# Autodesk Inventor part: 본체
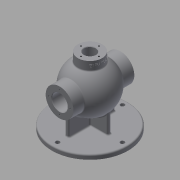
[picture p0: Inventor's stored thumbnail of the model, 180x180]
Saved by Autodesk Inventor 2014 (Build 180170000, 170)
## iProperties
Created: 2020-08
Part Number: 본체
Material: Generic
Document SubType Name: Modeling
Designer: kh
Density: 1 g/cm^3
Appearance: Default
Mass: 648.932 g
Surface Area: 1343.83 cm^2
Volume: 648.932 cm^3
Author: kh
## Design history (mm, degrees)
sketch "Sketch1"
  geometry: C1 r 85 at (0, 0); 1 further point
  constraints: 1 centre point, 1 coincident
  dimensions: "d0" = 170 diameter of C1
extrude "Extrusion1" new body sketch "Sketch1" distance "d1" = 10; taper "d2" = 0 deg
sketch "Sketch3"
  geometry: L1 (-53, 85)-(53, 85); L2 (-53, 85)-(-43, 85); L3 (43, 85)-(53, 85); A1 r 53 centre (0, 85) between (-53, 85) and (53, 85); A2 r 43 centre (0, 85) between (-43, 85) and (43, 85); 1 further point
  constraints: 6 end point, 4 point on circle, 2 centre point, 2 midpoint, 2 point on line, 1 collinear, 1 horizontal, 1 vertical alignment
  dimensions: "d22" = 106 diameter of A1; "d23" = 85 distance of point (0, 0) A1.centre; "d38" = 86 diameter of A2
revolve "Revolution4" sketch "Sketch3" stored, may be unused: angle "d39" = 90 deg
sketch "Sketch4"
  geometry: L1 (-85.514, 85)-(85.514, 85); L2 (-52, 102.5)-(-68, 102.5); L3 (-68, 102.5)-(-68, 116); L4 (-52, 102.5)-(-52, 103.5); L5 (-52, 103.5)-(-50.25, 103.5); L6 (-50.25, 103.5)-(-50.25, 102.5); L7 (68, 102.5)-(68, 116); L8 (-68, 102.5)-(-68, 85); L9 (68, 102.5)-(68, 85); L10 (68, 116)-(29.799, 116); L11 (-29.799, 116)-(-68, 116); L12 (0, 0)-(0, 159.663); L13 (-50.25, 102.5)-(-39.278, 102.5); L14 (39.278, 102.5)-(68, 102.5); C1 r 53 at (0, 85) reference; A1 r 43 centre (0, 85) between (-29.799, 116) and (-39.278, 102.5) reference; A2 r 43 centre (0, 85) between (29.799, 116) and (-29.799, 116); A3 r 43 centre (0, 85) between (39.278, 102.5) and (-39.278, 102.5); 2 further points
  constraints: 28 end point, 7 perpendicular, 7 point on circle, 6 parallel, 3 coincident, 3 collinear, 2 centre point, 2 point on line, 1 horizontal, 1 midpoint, 1 vertical alignment, 1 other
  dimensions: "d27" = 136 distance between parallel lines of L7 L3; "d29" = 16 distance of L2.start L2.end; "d30" = 1.75 distance of L4.end L5.end; "d31" = 37 diameter of L5 L1; "d41" = 62 diameter of L10 L1; "d42" = 35 diameter of L14 L1
revolve "Revolution2" stored, may be unused: angle "d32" = 90 deg
workplane "Work Plane1"
sketch "Sketch5"
  geometry: C1 r 27 at (0, 0); 1 further point
  constraints: 1 centre point, 1 coincident
  dimensions: "d35" = 54 diameter of C1
extrude "Extrusion2" join sketch "Sketch5" stored distance "d36" = 10; taper "d37" = 0 deg
revolve "Revolution5" stored, may be unused: angle "d43" = 90 deg
hole "Hole1" diameter "d46" = 26; stored, may be unused: countersink angle "d50" = 90 deg, drill point angle "d52" = 118 deg; dims "d44" = 10, "d45" = 10, "d47" = 6, "d48" = 4, "d49" = 2, "d51" = 8
chamfer "Chamfer1" distance "d53" = 1; stored, may be unused: second distance "d54" = 2, angle "d55" = 45 deg
sketch "Sketch6"
  geometry: C1 r 27 at (0, 0) reference; 2 further points
  constraints: 1 vertical alignment
  dimensions: "d56" = 20 distance of point (0, 20) point (0, 0)
hole "Hole2" sketch "Sketch6" at (0, 20) diameter "d57" = 3.459; stored, may be unused: countersink angle "d61" = 90 deg, drill point angle "d63" = 118 deg; dims "d58" = 12, "d59" = 4, "d60" = 2, "d62" = 15
pattern_circular "Circular Pattern1" dims angle "d65" = 360 deg
sketch "Sketch7"
  geometry: C1 r 31 at (0, 0) reference; 2 further points
  constraints: 1 vertical alignment
  dimensions: "d67" = 24 distance of C1.centre point (0, 24)
hole "Hole3" sketch "Sketch7" at (0, 24) diameter "d68" = 3.459; stored, may be unused: countersink angle "d72" = 90 deg, drill point angle "d74" = 118 deg; dims "d69" = 12, "d70" = 4, "d71" = 2, "d73" = 15
pattern_circular "Circular Pattern2" dims angle "d76" = 360 deg
mirror "Mirror1"
sketch "Sketch8"
  geometry: L1 (4, -52)-(-4, -52); L2 (-4, -52)-(-4, 52); L3 (-4, 52)-(4, 52); L4 (4, 52)-(4, -52); L5 (4, -52)-(-4, 52); L6 (-4, -52)-(4, 52); L7 (-43, -4)-(43, -4); L8 (43, -4)-(43, 4); L9 (43, 4)-(-43, 4); L10 (-43, 4)-(-43, -4); L11 (-43, -4)-(43, 4); L12 (43, -4)-(-43, 4); 1 further point
  constraints: 24 end point, 4 midpoint, 4 parallel, 2 horizontal, 2 perpendicular
  dimensions: "d78" = 8 distance of L7.end L8.end; "d79" = 8 distance of L2.end L3.end; "d80" = 86 distance of L7.start L7.end; "d81" = 104 distance of L3.end L1.start
extrude "Extrusion3" join sketch "Sketch8" stored distance "d82" = 10; taper "d83" = 0 deg
fillet "Fillet1" dims "d84" = 3
fillet "Fillet2" dims "d85" = 3
workplane "Work Plane2"
sketch "Sketch10"
  geometry: 2 further points
  constraints: 1 vertical alignment
  dimensions: "d90" = 72.5 distance of point (0, 0) point (0, 72.5)
hole "Hole4" sketch "Sketch10" at (0, 72.5) diameter "d91" = 9; stored, may be unused: countersink angle "d95" = 90 deg, drill point angle "d97" = 118 deg; dims "d92" = 12, "d93" = 4, "d94" = 2, "d96" = 15
pattern_circular "Circular Pattern3" dims angle "d99" = 360 deg
workplane "Work Plane3"
sketch "Sketch11"
  geometry: L1 (-20.739, -5.998)-(20.739, -5.998); L2 (20.739, -5.998)-(20.739, -12.002); L3 (20.739, -12.002)-(-20.739, -12.002); L4 (-20.739, -12.002)-(-20.739, -5.998); L5 (-20.739, -5.998)-(20.739, -12.002); L6 (-27, 0)-(-27, -17.714) reference; L7 (-27, 0)-(27, 0) reference; 2 further points
  constraints: 2 end point, 1 midpoint, 2 other
  dimensions: "d101" = 27 horizontal distance of L6.start point (0, -9); "d102" = 9 distance from line of L7 point (0, -9)
emboss "Emboss2" sketch "Sketch11" dims "d35" = 54, "d103" = 0.5, "d104" = 0
body "Solid1"
other parameters: "d26" = 35, "d28" = 62
